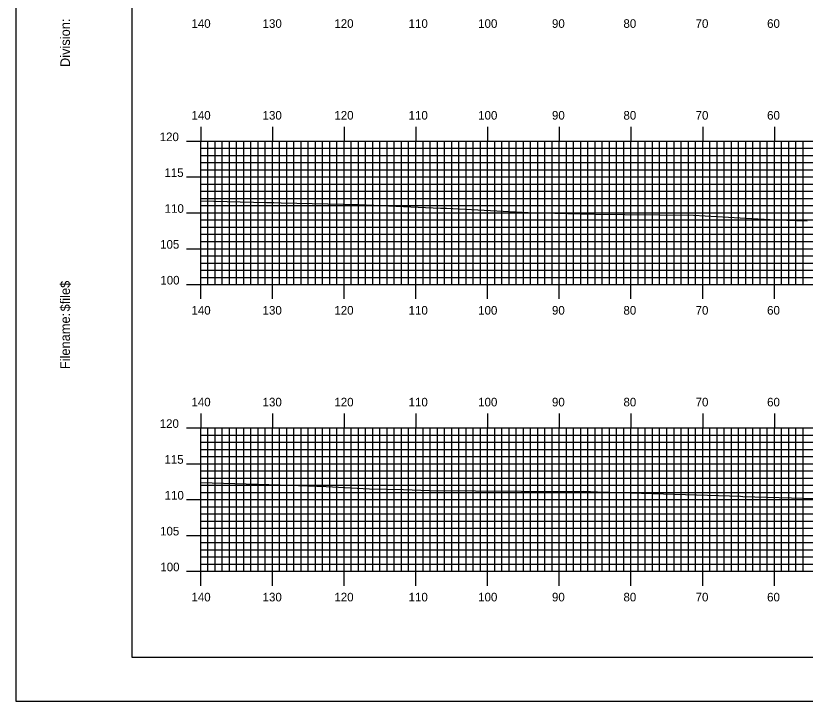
# Model space of a CAD drawing. Extents: x 1773203 to 1773546, y 442591 to 442811.
# Drawn here: x 1773202.8 to 1773312.9, y 442590.5 to 442686.2 of the extents above; entities that cross this region are included whole.
import ezdxf

# ---------------------------------------------------------------- set-up
doc = ezdxf.new("R2010")
doc.units = 0
for name, color, linetype in [('BORDER', 7, 'Continuous'), ('H_V ANNOTATION', 7, 'Continuous'), ('MAJOR', 7, 'Continuous'), ('MINOR', 7, 'Continuous'), ('PLOT BOUNDARY', 7, 'Continuous'), ('S_Roadway_Centerline', 7, 'Continuous')]:
    doc.layers.add(name, color=color, linetype=linetype)

msp = doc.modelspace()

# ---------------------------------------------------------------- linework, layer by layer
at = {"layer": 'BORDER'}
msp.add_lwpolyline([(1773219.03, 442596.67), (1773539.03, 442596.67), (1773539.03, 442806.67), (1773219.03, 442806.67)], close=True, dxfattribs=at)
at = {"layer": 'MAJOR'}
for p, q in [((1773228.63, 442670.67), (1773228.63, 442668.67)), ((1773238.63, 442670.67), (1773238.63, 442668.67)), ((1773248.63, 442670.67), (1773248.63, 442668.67)), ((1773258.63, 442670.67), (1773258.63, 442668.67)), ((1773268.63, 442670.67), (1773268.63, 442668.67)), ((1773278.63, 442670.67), (1773278.63, 442668.67)), ((1773288.63, 442670.67), (1773288.63, 442668.67)), ((1773298.63, 442670.67), (1773298.63, 442668.67)), ((1773308.63, 442670.67), (1773308.63, 442668.67)), ((1773226.63, 442668.67), (1773228.63, 442668.67)), ((1773228.63, 442668.67), (1773508.63, 442668.67)), ((1773228.63, 442648.67), (1773228.63, 442668.67)), ((1773228.63, 442648.67), (1773228.63, 442668.67)), ((1773228.63, 442668.67), (1773508.63, 442668.67)), ((1773238.63, 442648.67), (1773238.63, 442668.67)), ((1773248.63, 442648.67), (1773248.63, 442668.67)), ((1773258.63, 442648.67), (1773258.63, 442668.67)), ((1773268.63, 442648.67), (1773268.63, 442668.67)), ((1773278.63, 442648.67), (1773278.63, 442668.67)), ((1773288.63, 442648.67), (1773288.63, 442668.67)), ((1773298.63, 442648.67), (1773298.63, 442668.67)), ((1773308.63, 442648.67), (1773308.63, 442668.67)), ((1773226.63, 442663.67), (1773228.63, 442663.67)), ((1773228.63, 442663.67), (1773508.63, 442663.67)), ((1773226.63, 442658.67), (1773228.63, 442658.67)), ((1773228.63, 442658.67), (1773508.63, 442658.67)), ((1773226.63, 442653.67), (1773228.63, 442653.67)), ((1773228.63, 442653.67), (1773508.63, 442653.67)), ((1773226.63, 442648.67), (1773228.63, 442648.67)), ((1773228.63, 442648.67), (1773508.63, 442648.67)), ((1773228.63, 442648.67), (1773508.63, 442648.67)), ((1773228.63, 442646.66), (1773228.63, 442648.67)), ((1773238.63, 442646.66), (1773238.63, 442648.67)), ((1773248.63, 442646.66), (1773248.63, 442648.67)), ((1773258.63, 442646.66), (1773258.63, 442648.67)), ((1773268.63, 442646.66), (1773268.63, 442648.67)), ((1773278.63, 442646.66), (1773278.63, 442648.67)), ((1773288.63, 442646.66), (1773288.63, 442648.67)), ((1773298.63, 442646.66), (1773298.63, 442648.67)), ((1773308.63, 442646.66), (1773308.63, 442648.67)), ((1773228.63, 442630.67), (1773228.63, 442628.67)), ((1773238.63, 442630.67), (1773238.63, 442628.67)), ((1773248.63, 442630.67), (1773248.63, 442628.67)), ((1773258.63, 442630.67), (1773258.63, 442628.67)), ((1773268.63, 442630.67), (1773268.63, 442628.67)), ((1773278.63, 442630.67), (1773278.63, 442628.67)), ((1773288.63, 442630.67), (1773288.63, 442628.67)), ((1773298.63, 442630.67), (1773298.63, 442628.67)), ((1773308.63, 442630.67), (1773308.63, 442628.67)), ((1773226.63, 442628.67), (1773228.63, 442628.67)), ((1773228.63, 442628.67), (1773508.63, 442628.67)), ((1773228.63, 442608.67), (1773228.63, 442628.67)), ((1773228.63, 442608.67), (1773228.63, 442628.67)), ((1773228.63, 442628.67), (1773508.63, 442628.67)), ((1773238.63, 442608.67), (1773238.63, 442628.67)), ((1773248.63, 442608.67), (1773248.63, 442628.67)), ((1773258.63, 442608.67), (1773258.63, 442628.67)), ((1773268.63, 442608.67), (1773268.63, 442628.67)), ((1773278.63, 442608.67), (1773278.63, 442628.67)), ((1773288.63, 442608.67), (1773288.63, 442628.67)), ((1773298.63, 442608.67), (1773298.63, 442628.67)), ((1773308.63, 442608.67), (1773308.63, 442628.67)), ((1773226.63, 442623.67), (1773228.63, 442623.67)), ((1773228.63, 442623.67), (1773508.63, 442623.67)), ((1773226.63, 442618.67), (1773228.63, 442618.67)), ((1773228.63, 442618.67), (1773508.63, 442618.67)), ((1773226.63, 442613.67), (1773228.63, 442613.67)), ((1773228.63, 442613.67), (1773508.63, 442613.67)), ((1773226.63, 442608.67), (1773228.63, 442608.67)), ((1773228.63, 442608.67), (1773508.63, 442608.67)), ((1773228.63, 442608.67), (1773508.63, 442608.67)), ((1773228.63, 442606.66), (1773228.63, 442608.67)), ((1773238.63, 442606.66), (1773238.63, 442608.67)), ((1773248.63, 442606.66), (1773248.63, 442608.67)), ((1773258.63, 442606.66), (1773258.63, 442608.67)), ((1773268.63, 442606.66), (1773268.63, 442608.67)), ((1773278.63, 442606.66), (1773278.63, 442608.67)), ((1773288.63, 442606.66), (1773288.63, 442608.67)), ((1773298.63, 442606.66), (1773298.63, 442608.67)), ((1773308.63, 442606.66), (1773308.63, 442608.67))]:
    msp.add_line(p, q, dxfattribs=at)
at = {"layer": 'MINOR'}
for p, q in [((1773229.63, 442648.67), (1773229.63, 442668.67)), ((1773230.63, 442648.67), (1773230.63, 442668.67)), ((1773231.63, 442648.67), (1773231.63, 442668.67)), ((1773232.63, 442648.67), (1773232.63, 442668.67)), ((1773233.63, 442648.67), (1773233.63, 442668.67)), ((1773234.63, 442648.67), (1773234.63, 442668.67)), ((1773235.63, 442648.67), (1773235.63, 442668.67)), ((1773236.63, 442648.67), (1773236.63, 442668.67)), ((1773237.63, 442648.67), (1773237.63, 442668.67)), ((1773239.63, 442648.67), (1773239.63, 442668.67)), ((1773240.63, 442648.67), (1773240.63, 442668.67)), ((1773241.63, 442648.67), (1773241.63, 442668.67)), ((1773242.63, 442648.67), (1773242.63, 442668.67)), ((1773243.63, 442648.67), (1773243.63, 442668.67)), ((1773244.63, 442648.67), (1773244.63, 442668.67)), ((1773245.63, 442648.67), (1773245.63, 442668.67)), ((1773246.63, 442648.67), (1773246.63, 442668.67)), ((1773247.63, 442648.67), (1773247.63, 442668.67)), ((1773249.63, 442648.67), (1773249.63, 442668.67)), ((1773250.63, 442648.67), (1773250.63, 442668.67)), ((1773251.63, 442648.67), (1773251.63, 442668.67)), ((1773252.63, 442648.67), (1773252.63, 442668.67)), ((1773253.63, 442648.67), (1773253.63, 442668.67)), ((1773254.63, 442648.67), (1773254.63, 442668.67)), ((1773255.63, 442648.67), (1773255.63, 442668.67)), ((1773256.63, 442648.67), (1773256.63, 442668.67)), ((1773257.63, 442648.67), (1773257.63, 442668.67)), ((1773259.63, 442648.67), (1773259.63, 442668.67)), ((1773260.63, 442648.67), (1773260.63, 442668.67)), ((1773261.63, 442648.67), (1773261.63, 442668.67)), ((1773262.63, 442648.67), (1773262.63, 442668.67)), ((1773263.63, 442648.67), (1773263.63, 442668.67)), ((1773264.63, 442648.67), (1773264.63, 442668.67)), ((1773265.63, 442648.67), (1773265.63, 442668.67)), ((1773266.63, 442648.67), (1773266.63, 442668.67)), ((1773267.63, 442648.67), (1773267.63, 442668.67)), ((1773269.63, 442648.67), (1773269.63, 442668.67)), ((1773270.63, 442648.67), (1773270.63, 442668.67)), ((1773271.63, 442648.67), (1773271.63, 442668.67)), ((1773272.63, 442648.67), (1773272.63, 442668.67)), ((1773273.63, 442648.67), (1773273.63, 442668.67)), ((1773274.63, 442648.67), (1773274.63, 442668.67)), ((1773275.63, 442648.67), (1773275.63, 442668.67)), ((1773276.63, 442648.67), (1773276.63, 442668.67)), ((1773277.63, 442648.67), (1773277.63, 442668.67)), ((1773279.63, 442648.67), (1773279.63, 442668.67)), ((1773280.63, 442648.67), (1773280.63, 442668.67)), ((1773281.63, 442648.67), (1773281.63, 442668.67)), ((1773282.63, 442648.67), (1773282.63, 442668.67)), ((1773283.63, 442648.67), (1773283.63, 442668.67)), ((1773284.63, 442648.67), (1773284.63, 442668.67)), ((1773285.63, 442648.67), (1773285.63, 442668.67)), ((1773286.63, 442648.67), (1773286.63, 442668.67)), ((1773287.63, 442648.67), (1773287.63, 442668.67)), ((1773289.63, 442648.67), (1773289.63, 442668.67)), ((1773290.63, 442648.67), (1773290.63, 442668.67)), ((1773291.63, 442648.67), (1773291.63, 442668.67)), ((1773292.63, 442648.67), (1773292.63, 442668.67)), ((1773293.63, 442648.67), (1773293.63, 442668.67)), ((1773294.63, 442648.67), (1773294.63, 442668.67)), ((1773295.63, 442648.67), (1773295.63, 442668.67)), ((1773296.63, 442648.67), (1773296.63, 442668.67)), ((1773297.63, 442648.67), (1773297.63, 442668.67)), ((1773299.63, 442648.67), (1773299.63, 442668.67)), ((1773300.63, 442648.67), (1773300.63, 442668.67)), ((1773301.63, 442648.67), (1773301.63, 442668.67)), ((1773302.63, 442648.67), (1773302.63, 442668.67)), ((1773303.63, 442648.67), (1773303.63, 442668.67)), ((1773304.63, 442648.67), (1773304.63, 442668.67)), ((1773305.63, 442648.67), (1773305.63, 442668.67)), ((1773306.63, 442648.67), (1773306.63, 442668.67)), ((1773307.63, 442648.67), (1773307.63, 442668.67)), ((1773309.63, 442648.67), (1773309.63, 442668.67)), ((1773310.63, 442648.67), (1773310.63, 442668.67)), ((1773311.63, 442648.67), (1773311.63, 442668.67)), ((1773312.63, 442648.67), (1773312.63, 442668.67)), ((1773228.63, 442667.67), (1773508.63, 442667.67)), ((1773228.63, 442667.67), (1773230.64, 442667.67)), ((1773228.63, 442666.67), (1773508.63, 442666.67)), ((1773228.63, 442666.67), (1773230.64, 442666.67)), ((1773228.63, 442665.67), (1773508.63, 442665.67)), ((1773228.63, 442665.67), (1773230.64, 442665.67)), ((1773228.63, 442664.67), (1773508.63, 442664.67)), ((1773228.63, 442664.67), (1773230.64, 442664.67)), ((1773228.63, 442662.67), (1773508.63, 442662.67)), ((1773228.63, 442662.67), (1773230.64, 442662.67)), ((1773228.63, 442661.67), (1773508.63, 442661.67)), ((1773228.63, 442661.67), (1773230.64, 442661.67)), ((1773228.63, 442660.67), (1773508.63, 442660.67)), ((1773228.63, 442660.67), (1773230.64, 442660.67)), ((1773228.63, 442659.67), (1773508.63, 442659.67)), ((1773228.63, 442659.67), (1773230.64, 442659.67)), ((1773228.63, 442657.67), (1773508.63, 442657.67)), ((1773228.63, 442657.67), (1773230.64, 442657.67)), ((1773228.63, 442656.67), (1773508.63, 442656.67)), ((1773228.63, 442656.67), (1773230.64, 442656.67)), ((1773228.63, 442655.67), (1773508.63, 442655.67)), ((1773228.63, 442655.67), (1773230.64, 442655.67)), ((1773228.63, 442654.67), (1773508.63, 442654.67)), ((1773228.63, 442654.67), (1773230.64, 442654.67)), ((1773228.63, 442652.67), (1773508.63, 442652.67)), ((1773228.63, 442652.67), (1773230.64, 442652.67)), ((1773228.63, 442651.67), (1773508.63, 442651.67)), ((1773228.63, 442651.67), (1773230.64, 442651.67)), ((1773228.63, 442650.67), (1773508.63, 442650.67)), ((1773228.63, 442650.67), (1773230.64, 442650.67)), ((1773228.63, 442649.67), (1773508.63, 442649.67)), ((1773228.63, 442649.67), (1773230.64, 442649.67)), ((1773229.63, 442608.67), (1773229.63, 442628.67)), ((1773230.63, 442608.67), (1773230.63, 442628.67)), ((1773231.63, 442608.67), (1773231.63, 442628.67)), ((1773232.63, 442608.67), (1773232.63, 442628.67)), ((1773233.63, 442608.67), (1773233.63, 442628.67)), ((1773234.63, 442608.67), (1773234.63, 442628.67)), ((1773235.63, 442608.67), (1773235.63, 442628.67)), ((1773236.63, 442608.67), (1773236.63, 442628.67)), ((1773237.63, 442608.67), (1773237.63, 442628.67)), ((1773239.63, 442608.67), (1773239.63, 442628.67)), ((1773240.63, 442608.67), (1773240.63, 442628.67)), ((1773241.63, 442608.67), (1773241.63, 442628.67)), ((1773242.63, 442608.67), (1773242.63, 442628.67)), ((1773243.63, 442608.67), (1773243.63, 442628.67)), ((1773244.63, 442608.67), (1773244.63, 442628.67)), ((1773245.63, 442608.67), (1773245.63, 442628.67)), ((1773246.63, 442608.67), (1773246.63, 442628.67)), ((1773247.63, 442608.67), (1773247.63, 442628.67)), ((1773249.63, 442608.67), (1773249.63, 442628.67)), ((1773250.63, 442608.67), (1773250.63, 442628.67)), ((1773251.63, 442608.67), (1773251.63, 442628.67)), ((1773252.63, 442608.67), (1773252.63, 442628.67)), ((1773253.63, 442608.67), (1773253.63, 442628.67)), ((1773254.63, 442608.67), (1773254.63, 442628.67)), ((1773255.63, 442608.67), (1773255.63, 442628.67)), ((1773256.63, 442608.67), (1773256.63, 442628.67)), ((1773257.63, 442608.67), (1773257.63, 442628.67)), ((1773259.63, 442608.67), (1773259.63, 442628.67)), ((1773260.63, 442608.67), (1773260.63, 442628.67)), ((1773261.63, 442608.67), (1773261.63, 442628.67)), ((1773262.63, 442608.67), (1773262.63, 442628.67)), ((1773263.63, 442608.67), (1773263.63, 442628.67)), ((1773264.63, 442608.67), (1773264.63, 442628.67)), ((1773265.63, 442608.67), (1773265.63, 442628.67)), ((1773266.63, 442608.67), (1773266.63, 442628.67)), ((1773267.63, 442608.67), (1773267.63, 442628.67)), ((1773269.63, 442608.67), (1773269.63, 442628.67)), ((1773270.63, 442608.67), (1773270.63, 442628.67)), ((1773271.63, 442608.67), (1773271.63, 442628.67)), ((1773272.63, 442608.67), (1773272.63, 442628.67)), ((1773273.63, 442608.67), (1773273.63, 442628.67)), ((1773274.63, 442608.67), (1773274.63, 442628.67)), ((1773275.63, 442608.67), (1773275.63, 442628.67)), ((1773276.63, 442608.67), (1773276.63, 442628.67)), ((1773277.63, 442608.67), (1773277.63, 442628.67)), ((1773279.63, 442608.67), (1773279.63, 442628.67)), ((1773280.63, 442608.67), (1773280.63, 442628.67)), ((1773281.63, 442608.67), (1773281.63, 442628.67)), ((1773282.63, 442608.67), (1773282.63, 442628.67)), ((1773283.63, 442608.67), (1773283.63, 442628.67)), ((1773284.63, 442608.67), (1773284.63, 442628.67)), ((1773285.63, 442608.67), (1773285.63, 442628.67)), ((1773286.63, 442608.67), (1773286.63, 442628.67)), ((1773287.63, 442608.67), (1773287.63, 442628.67)), ((1773289.63, 442608.67), (1773289.63, 442628.67)), ((1773290.63, 442608.67), (1773290.63, 442628.67)), ((1773291.63, 442608.67), (1773291.63, 442628.67)), ((1773292.63, 442608.67), (1773292.63, 442628.67)), ((1773293.63, 442608.67), (1773293.63, 442628.67)), ((1773294.63, 442608.67), (1773294.63, 442628.67)), ((1773295.63, 442608.67), (1773295.63, 442628.67)), ((1773296.63, 442608.67), (1773296.63, 442628.67)), ((1773297.63, 442608.67), (1773297.63, 442628.67)), ((1773299.63, 442608.67), (1773299.63, 442628.67)), ((1773300.63, 442608.67), (1773300.63, 442628.67)), ((1773301.63, 442608.67), (1773301.63, 442628.67)), ((1773302.63, 442608.67), (1773302.63, 442628.67)), ((1773303.63, 442608.67), (1773303.63, 442628.67)), ((1773304.63, 442608.67), (1773304.63, 442628.67)), ((1773305.63, 442608.67), (1773305.63, 442628.67)), ((1773306.63, 442608.67), (1773306.63, 442628.67)), ((1773307.63, 442608.67), (1773307.63, 442628.67)), ((1773309.63, 442608.67), (1773309.63, 442628.67)), ((1773310.63, 442608.67), (1773310.63, 442628.67)), ((1773311.63, 442608.67), (1773311.63, 442628.67)), ((1773312.63, 442608.67), (1773312.63, 442628.67)), ((1773228.63, 442627.67), (1773508.63, 442627.67)), ((1773228.63, 442627.67), (1773230.64, 442627.67)), ((1773228.63, 442626.67), (1773508.63, 442626.67)), ((1773228.63, 442626.67), (1773230.64, 442626.67)), ((1773228.63, 442625.67), (1773508.63, 442625.67)), ((1773228.63, 442625.67), (1773230.64, 442625.67)), ((1773228.63, 442624.67), (1773508.63, 442624.67)), ((1773228.63, 442624.67), (1773230.64, 442624.67)), ((1773228.63, 442622.67), (1773508.63, 442622.67)), ((1773228.63, 442622.67), (1773230.64, 442622.67)), ((1773228.63, 442621.67), (1773508.63, 442621.67)), ((1773228.63, 442621.67), (1773230.64, 442621.67)), ((1773228.63, 442620.67), (1773508.63, 442620.67)), ((1773228.63, 442620.67), (1773230.64, 442620.67)), ((1773228.63, 442619.67), (1773508.63, 442619.67)), ((1773228.63, 442619.67), (1773230.64, 442619.67)), ((1773228.63, 442617.67), (1773508.63, 442617.67)), ((1773228.63, 442617.67), (1773230.64, 442617.67)), ((1773228.63, 442616.67), (1773508.63, 442616.67)), ((1773228.63, 442616.67), (1773230.64, 442616.67)), ((1773228.63, 442615.67), (1773508.63, 442615.67)), ((1773228.63, 442615.67), (1773230.64, 442615.67)), ((1773228.63, 442614.67), (1773508.63, 442614.67)), ((1773228.63, 442614.67), (1773230.64, 442614.67)), ((1773228.63, 442612.67), (1773508.63, 442612.67)), ((1773228.63, 442612.67), (1773230.64, 442612.67)), ((1773228.63, 442611.67), (1773508.63, 442611.67)), ((1773228.63, 442611.67), (1773230.64, 442611.67)), ((1773228.63, 442610.67), (1773508.63, 442610.67)), ((1773228.63, 442610.67), (1773230.64, 442610.67)), ((1773228.63, 442609.67), (1773508.63, 442609.67)), ((1773228.63, 442609.67), (1773230.64, 442609.67))]:
    msp.add_line(p, q, dxfattribs=at)
at = {"layer": 'PLOT BOUNDARY'}
msp.add_lwpolyline([(1773202.85, 442590.55), (1773542.85, 442590.55), (1773542.85, 442810.55), (1773202.85, 442810.55)], close=True, dxfattribs=at)
at = {"layer": 'S_Roadway_Centerline'}
for points in [[(1773228.63, 442660.36), (1773237.82, 442660.12), (1773238.84, 442660.09), (1773239.86, 442660.07), (1773250.67, 442659.82), (1773262.08, 442659.33), (1773262.89, 442659.3), (1773274.28, 442658.71), (1773283.56, 442658.5), (1773287.79, 442658.45), (1773297.33, 442658.35), (1773305.48, 442657.88), (1773308.94, 442657.68), (1773313.18, 442657.56)], [(1773228.63, 442621.06), (1773239.72, 442620.71), (1773246.12, 442620.49), (1773252.15, 442620.19), (1773256.92, 442620.1), (1773260.55, 442619.92), (1773279.79, 442619.79), (1773282.02, 442619.84), (1773283.95, 442619.74), (1773303.9, 442619.13), (1773304.25, 442619.12), (1773316.06, 442618.77)]]:
    msp.add_lwpolyline(points, dxfattribs=at)

# ---------------------------------------------------------------- texts
at = {"layer": 'BORDER'}
for s, p in [('Division:', (1773210.4, 442679)), ('$file$', (1773210.4, 442644.92)), ('Filename:', (1773210.4, 442636.86))]:
    msp.add_text(s, height=1.339, rotation=90, dxfattribs=at).set_placement(p)
at = {"layer": 'H_V ANNOTATION'}
for s, p in [('140', (1773227.34, 442684.47)), ('130', (1773237.26, 442684.47)), ('120', (1773247.27, 442684.47)), ('110', (1773257.62, 442684.47)), ('100', (1773267.32, 442684.47)), ('90', (1773277.61, 442684.47)), ('80', (1773287.58, 442684.47)), ('70', (1773297.64, 442684.47)), ('60', (1773307.61, 442684.47)), ('140', (1773227.34, 442671.67)), ('130', (1773237.26, 442671.67)), ('120', (1773247.27, 442671.67)), ('110', (1773257.62, 442671.67)), ('100', (1773267.32, 442671.67)), ('90', (1773277.61, 442671.67)), ('80', (1773287.58, 442671.67)), ('70', (1773297.64, 442671.67)), ('60', (1773307.61, 442671.67)), ('120', (1773222.91, 442668.67)), ('115', (1773223.57, 442663.67)), ('110', (1773223.6, 442658.67)), ('105', (1773222.97, 442653.67)), ('100', (1773223, 442648.67)), ('140', (1773227.34, 442644.47)), ('130', (1773237.26, 442644.47)), ('120', (1773247.27, 442644.47)), ('110', (1773257.62, 442644.47)), ('100', (1773267.32, 442644.47)), ('90', (1773277.61, 442644.47)), ('80', (1773287.58, 442644.47)), ('70', (1773297.64, 442644.47)), ('60', (1773307.61, 442644.47)), ('140', (1773227.34, 442631.67)), ('130', (1773237.26, 442631.67)), ('120', (1773247.27, 442631.67)), ('110', (1773257.62, 442631.67)), ('100', (1773267.32, 442631.67)), ('90', (1773277.61, 442631.67)), ('80', (1773287.58, 442631.67)), ('70', (1773297.64, 442631.67)), ('60', (1773307.61, 442631.67)), ('120', (1773222.91, 442628.67)), ('115', (1773223.57, 442623.67)), ('110', (1773223.6, 442618.67)), ('105', (1773222.97, 442613.67)), ('100', (1773223, 442608.67)), ('140', (1773227.34, 442604.47)), ('130', (1773237.26, 442604.47)), ('120', (1773247.27, 442604.47)), ('110', (1773257.62, 442604.47)), ('100', (1773267.32, 442604.47)), ('90', (1773277.61, 442604.47)), ('80', (1773287.58, 442604.47)), ('70', (1773297.64, 442604.47)), ('60', (1773307.61, 442604.47))]:
    msp.add_text(s, height=1.2, dxfattribs=at).set_placement(p)
at = {"layer": 'MAJOR'}
for p in [(1773228.62, 442648.67), (1773228.62, 442608.67)]:
    msp.add_text('-', height=0.012, dxfattribs=at).set_placement(p)

doc.saveas('drawing.dxf')
